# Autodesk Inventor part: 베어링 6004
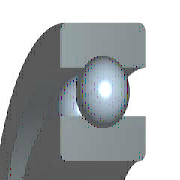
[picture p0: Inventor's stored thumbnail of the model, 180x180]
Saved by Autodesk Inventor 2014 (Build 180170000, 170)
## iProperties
IsCustomPart: 1
Created: 2012-02
Part Number: 베어링 6004
Material: 강철, 연강
Description: 깊은 그루브 볼 베어링
Document SubType Name: Modeling
Standard: KS B 2023
Designer: mduedu
Standards Organization: KS
Language: ko-KR
Size Designation: 6004 - 20 x 42 x 12
Categories: <MemberInstance><Categories><Category DisplayName="샤프트 부품" InternalName="7f7aeb1f-a693-4053-b835-cee3144e0d98" Mnemonic="SHFT"><Category DisplayName="베어링" Inter
Density: 1 g/cm^3
Appearance: 노란색
Author: mduedu
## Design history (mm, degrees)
sketch "스케치" dims "d0" = 5.72 (= -0.26 x WD + 0.26 x BD)
  geometry: L1 (3.14, 15.5)-(8.86, 15.5); L2 (6, 15.5)-(6, 12.64); L3 (6, 15.5)-(6, 18.36); L4 (3.875, 13.586)-(0, 13.586); L5 (0, 10)-(12, 10); L6 (3.875, 17.414)-(0, 17.414); L7 (0, 21)-(12, 21); L8 (12, 10)-(12, 13.586); L9 (8.125, 13.586)-(12, 13.586); L10 (8.125, 17.414)-(12, 17.414); L11 (12, 21)-(12, 17.414); L12 (-1.4, 0)-(8.4, 0) reference; L13 (0, -0.3)-(0, 5.3) reference
  constraints: 22 end point, 4 point on line, 2 collinear, 2 perpendicular, 2 symmetric about line, 1 midpoint, 1 parallel, 14 other
  dimensions: "d9" = 20 diameter of L5 L12 (= WD); "d11" = 42 diameter of L7 L12 (= BD); "d12" = 12 distance between parallel lines of L8 L13 (= KB); "d13" = 27.172 diameter of L9 L12 (= 0.326 x BD + 0.674 x WD)
revolve "본체" stored, may be unused: angle "d6" = 90 deg
revolve "볼" stored, may be unused: angle "d7" = 90 deg
pattern_circular "IDS_ARRAYBALL[SIMPL:T]" dims angle "d3" = 360 deg
body "Solid1"
fillet "모깎기1" dims "d1" = 0.6 (= KRS)
other parameters: "WD" = 20 [user parameter; used in 5 equation terms], "BD" = 42 [user parameter; used in 5 equation terms], "KB" = 12 [user parameter; used in 1 equation term], "KRS" = 0.6 [user parameter; used in 1 equation term], "d4" = 0, "d5" = 0, "d8" = 0, "d14" = 0, "d15" = 0, "BBA" = 0 [user parameter], "BC0" = 5000000 [user parameter], "BC" = 9360000 [user parameter], "BR" = 21 (= 0.5 x BD) [user parameter]
